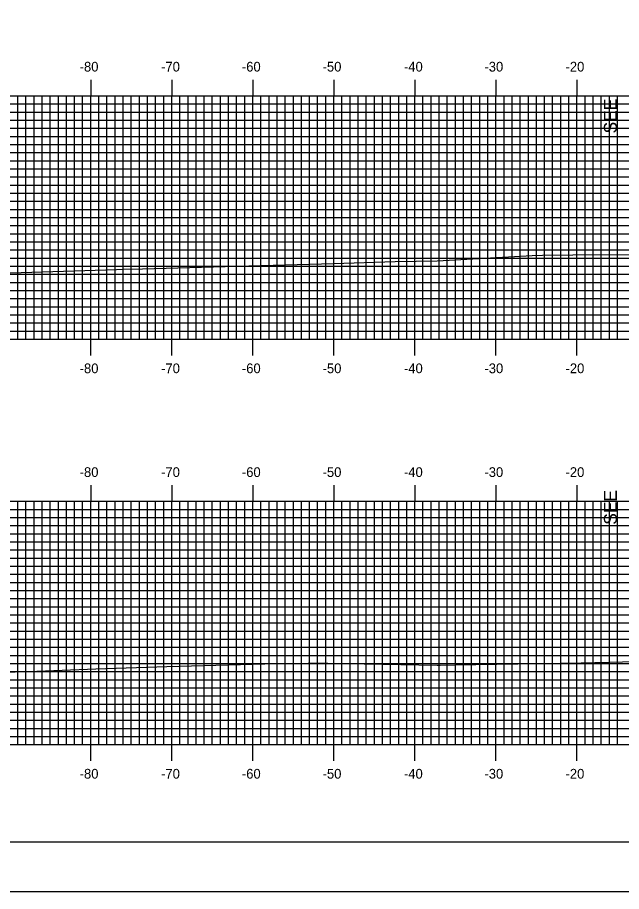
# Model space of a CAD drawing. Extents: x 1272 to 1616, y -1658 to -1438.
# Drawn here: x 1349.1 to 1423.7, y -1657.7 to -1549.9 of the extents above; entities that cross this region are included whole.
import ezdxf

# ---------------------------------------------------------------- set-up
doc = ezdxf.new("R2010")
doc.units = 0
for name, color, linetype in [('ANNOTATION', 7, 'Continuous'), ('BORDER', 7, 'Continuous'), ('H_V ANNOTATION', 7, 'Continuous'), ('MAJOR', 7, 'Continuous'), ('MINOR', 7, 'Continuous'), ('PLOT BOUNDARY', 7, 'Continuous'), ('S_Roadway_Centerline', 7, 'Continuous')]:
    doc.layers.add(name, color=color, linetype=linetype)

msp = doc.modelspace()

# ---------------------------------------------------------------- linework, layer by layer
at = {"layer": 'BORDER'}
msp.add_lwpolyline([(1288.56, -1651.6), (1608.56, -1651.6), (1608.56, -1441.6), (1288.56, -1441.6)], close=True, dxfattribs=at)
at = {"layer": 'MAJOR'}
for p, q in [((1358.16, -1557.6), (1358.16, -1559.6)), ((1368.16, -1557.6), (1368.16, -1559.6)), ((1378.16, -1557.6), (1378.16, -1559.6)), ((1388.16, -1557.6), (1388.16, -1559.6)), ((1398.16, -1557.6), (1398.16, -1559.6)), ((1408.16, -1557.6), (1408.16, -1559.6)), ((1418.16, -1557.6), (1418.16, -1559.6)), ((1298.16, -1559.6), (1578.16, -1559.6)), ((1298.16, -1559.6), (1578.16, -1559.6)), ((1358.16, -1589.6), (1358.16, -1559.6)), ((1368.16, -1589.6), (1368.16, -1559.6)), ((1378.16, -1589.6), (1378.16, -1559.6)), ((1388.16, -1589.6), (1388.16, -1559.6)), ((1398.16, -1589.6), (1398.16, -1559.6)), ((1408.16, -1589.6), (1408.16, -1559.6)), ((1418.16, -1589.6), (1418.16, -1559.6)), ((1298.16, -1564.6), (1578.16, -1564.6)), ((1298.16, -1569.6), (1578.16, -1569.6)), ((1298.16, -1574.6), (1578.16, -1574.6)), ((1298.16, -1579.6), (1578.16, -1579.6)), ((1298.16, -1584.6), (1578.16, -1584.6)), ((1298.16, -1589.6), (1578.16, -1589.6)), ((1298.16, -1589.6), (1578.16, -1589.6)), ((1358.16, -1591.61), (1358.16, -1589.6)), ((1368.16, -1591.61), (1368.16, -1589.6)), ((1378.16, -1591.61), (1378.16, -1589.6)), ((1388.16, -1591.61), (1388.16, -1589.6)), ((1398.16, -1591.61), (1398.16, -1589.6)), ((1408.16, -1591.61), (1408.16, -1589.6)), ((1418.16, -1591.61), (1418.16, -1589.6)), ((1358.16, -1607.6), (1358.16, -1609.6)), ((1368.16, -1607.6), (1368.16, -1609.6)), ((1378.16, -1607.6), (1378.16, -1609.6)), ((1388.16, -1607.6), (1388.16, -1609.6)), ((1398.16, -1607.6), (1398.16, -1609.6)), ((1408.16, -1607.6), (1408.16, -1609.6)), ((1418.16, -1607.6), (1418.16, -1609.6)), ((1298.16, -1609.6), (1578.16, -1609.6)), ((1298.16, -1609.6), (1578.16, -1609.6)), ((1358.16, -1639.6), (1358.16, -1609.6)), ((1368.16, -1639.6), (1368.16, -1609.6)), ((1378.16, -1639.6), (1378.16, -1609.6)), ((1388.16, -1639.6), (1388.16, -1609.6)), ((1398.16, -1639.6), (1398.16, -1609.6)), ((1408.16, -1639.6), (1408.16, -1609.6)), ((1418.16, -1639.6), (1418.16, -1609.6)), ((1298.16, -1614.6), (1578.16, -1614.6)), ((1298.16, -1619.6), (1578.16, -1619.6)), ((1298.16, -1624.6), (1578.16, -1624.6)), ((1298.16, -1629.6), (1578.16, -1629.6)), ((1298.16, -1634.6), (1578.16, -1634.6)), ((1298.16, -1639.6), (1578.16, -1639.6)), ((1298.16, -1639.6), (1578.16, -1639.6)), ((1358.16, -1641.61), (1358.16, -1639.6)), ((1368.16, -1641.61), (1368.16, -1639.6)), ((1378.16, -1641.61), (1378.16, -1639.6)), ((1388.16, -1641.61), (1388.16, -1639.6)), ((1398.16, -1641.61), (1398.16, -1639.6)), ((1408.16, -1641.61), (1408.16, -1639.6)), ((1418.16, -1641.61), (1418.16, -1639.6))]:
    msp.add_line(p, q, dxfattribs=at)
at = {"layer": 'MINOR'}
for p, q in [((1349.16, -1589.6), (1349.16, -1559.6)), ((1350.16, -1589.6), (1350.16, -1559.6)), ((1351.16, -1589.6), (1351.16, -1559.6)), ((1352.16, -1589.6), (1352.16, -1559.6)), ((1353.16, -1589.6), (1353.16, -1559.6)), ((1354.16, -1589.6), (1354.16, -1559.6)), ((1355.16, -1589.6), (1355.16, -1559.6)), ((1356.16, -1589.6), (1356.16, -1559.6)), ((1357.16, -1589.6), (1357.16, -1559.6)), ((1359.16, -1589.6), (1359.16, -1559.6)), ((1360.16, -1589.6), (1360.16, -1559.6)), ((1361.16, -1589.6), (1361.16, -1559.6)), ((1362.16, -1589.6), (1362.16, -1559.6)), ((1363.16, -1589.6), (1363.16, -1559.6)), ((1364.16, -1589.6), (1364.16, -1559.6)), ((1365.16, -1589.6), (1365.16, -1559.6)), ((1366.16, -1589.6), (1366.16, -1559.6)), ((1367.16, -1589.6), (1367.16, -1559.6)), ((1369.16, -1589.6), (1369.16, -1559.6)), ((1370.16, -1589.6), (1370.16, -1559.6)), ((1371.16, -1589.6), (1371.16, -1559.6)), ((1372.16, -1589.6), (1372.16, -1559.6)), ((1373.16, -1589.6), (1373.16, -1559.6)), ((1374.16, -1589.6), (1374.16, -1559.6)), ((1375.16, -1589.6), (1375.16, -1559.6)), ((1376.16, -1589.6), (1376.16, -1559.6)), ((1377.16, -1589.6), (1377.16, -1559.6)), ((1379.16, -1589.6), (1379.16, -1559.6)), ((1380.16, -1589.6), (1380.16, -1559.6)), ((1381.16, -1589.6), (1381.16, -1559.6)), ((1382.16, -1589.6), (1382.16, -1559.6)), ((1383.16, -1589.6), (1383.16, -1559.6)), ((1384.16, -1589.6), (1384.16, -1559.6)), ((1385.16, -1589.6), (1385.16, -1559.6)), ((1386.16, -1589.6), (1386.16, -1559.6)), ((1387.16, -1589.6), (1387.16, -1559.6)), ((1389.16, -1589.6), (1389.16, -1559.6)), ((1390.16, -1589.6), (1390.16, -1559.6)), ((1391.16, -1589.6), (1391.16, -1559.6)), ((1392.16, -1589.6), (1392.16, -1559.6)), ((1393.16, -1589.6), (1393.16, -1559.6)), ((1394.16, -1589.6), (1394.16, -1559.6)), ((1395.16, -1589.6), (1395.16, -1559.6)), ((1396.16, -1589.6), (1396.16, -1559.6)), ((1397.16, -1589.6), (1397.16, -1559.6)), ((1399.16, -1589.6), (1399.16, -1559.6)), ((1400.16, -1589.6), (1400.16, -1559.6)), ((1401.16, -1589.6), (1401.16, -1559.6)), ((1402.16, -1589.6), (1402.16, -1559.6)), ((1403.16, -1589.6), (1403.16, -1559.6)), ((1404.16, -1589.6), (1404.16, -1559.6)), ((1405.16, -1589.6), (1405.16, -1559.6)), ((1406.16, -1589.6), (1406.16, -1559.6)), ((1407.16, -1589.6), (1407.16, -1559.6)), ((1409.16, -1589.6), (1409.16, -1559.6)), ((1410.16, -1589.6), (1410.16, -1559.6)), ((1411.16, -1589.6), (1411.16, -1559.6)), ((1412.16, -1589.6), (1412.16, -1559.6)), ((1413.16, -1589.6), (1413.16, -1559.6)), ((1414.16, -1589.6), (1414.16, -1559.6)), ((1415.16, -1589.6), (1415.16, -1559.6)), ((1416.16, -1589.6), (1416.16, -1559.6)), ((1417.16, -1589.6), (1417.16, -1559.6)), ((1419.16, -1589.6), (1419.16, -1559.6)), ((1420.16, -1589.6), (1420.16, -1559.6)), ((1421.16, -1589.6), (1421.16, -1559.6)), ((1422.16, -1589.6), (1422.16, -1559.6)), ((1423.16, -1589.6), (1423.16, -1559.6)), ((1298.16, -1560.6), (1578.16, -1560.6)), ((1298.16, -1561.6), (1578.16, -1561.6)), ((1298.16, -1562.6), (1578.16, -1562.6)), ((1298.16, -1563.6), (1578.16, -1563.6)), ((1298.16, -1565.6), (1578.16, -1565.6)), ((1298.16, -1566.6), (1578.16, -1566.6)), ((1298.16, -1567.6), (1578.16, -1567.6)), ((1298.16, -1568.6), (1578.16, -1568.6)), ((1298.16, -1570.6), (1578.16, -1570.6)), ((1298.16, -1571.6), (1578.16, -1571.6)), ((1298.16, -1572.6), (1578.16, -1572.6)), ((1298.16, -1573.6), (1578.16, -1573.6)), ((1298.16, -1575.6), (1578.16, -1575.6)), ((1298.16, -1576.6), (1578.16, -1576.6)), ((1298.16, -1577.6), (1578.16, -1577.6)), ((1298.16, -1578.6), (1578.16, -1578.6)), ((1298.16, -1580.6), (1578.16, -1580.6)), ((1298.16, -1581.6), (1578.16, -1581.6)), ((1298.16, -1582.6), (1578.16, -1582.6)), ((1298.16, -1583.6), (1578.16, -1583.6)), ((1298.16, -1585.6), (1578.16, -1585.6)), ((1298.16, -1586.6), (1578.16, -1586.6)), ((1298.16, -1587.6), (1578.16, -1587.6)), ((1298.16, -1588.6), (1578.16, -1588.6)), ((1349.16, -1639.6), (1349.16, -1609.6)), ((1350.16, -1639.6), (1350.16, -1609.6)), ((1351.16, -1639.6), (1351.16, -1609.6)), ((1352.16, -1639.6), (1352.16, -1609.6)), ((1353.16, -1639.6), (1353.16, -1609.6)), ((1354.16, -1639.6), (1354.16, -1609.6)), ((1355.16, -1639.6), (1355.16, -1609.6)), ((1356.16, -1639.6), (1356.16, -1609.6)), ((1357.16, -1639.6), (1357.16, -1609.6)), ((1359.16, -1639.6), (1359.16, -1609.6)), ((1360.16, -1639.6), (1360.16, -1609.6)), ((1361.16, -1639.6), (1361.16, -1609.6)), ((1362.16, -1639.6), (1362.16, -1609.6)), ((1363.16, -1639.6), (1363.16, -1609.6)), ((1364.16, -1639.6), (1364.16, -1609.6)), ((1365.16, -1639.6), (1365.16, -1609.6)), ((1366.16, -1639.6), (1366.16, -1609.6)), ((1367.16, -1639.6), (1367.16, -1609.6)), ((1369.16, -1639.6), (1369.16, -1609.6)), ((1370.16, -1639.6), (1370.16, -1609.6)), ((1371.16, -1639.6), (1371.16, -1609.6)), ((1372.16, -1639.6), (1372.16, -1609.6)), ((1373.16, -1639.6), (1373.16, -1609.6)), ((1374.16, -1639.6), (1374.16, -1609.6)), ((1375.16, -1639.6), (1375.16, -1609.6)), ((1376.16, -1639.6), (1376.16, -1609.6)), ((1377.16, -1639.6), (1377.16, -1609.6)), ((1379.16, -1639.6), (1379.16, -1609.6)), ((1380.16, -1639.6), (1380.16, -1609.6)), ((1381.16, -1639.6), (1381.16, -1609.6)), ((1382.16, -1639.6), (1382.16, -1609.6)), ((1383.16, -1639.6), (1383.16, -1609.6)), ((1384.16, -1639.6), (1384.16, -1609.6)), ((1385.16, -1639.6), (1385.16, -1609.6)), ((1386.16, -1639.6), (1386.16, -1609.6)), ((1387.16, -1639.6), (1387.16, -1609.6)), ((1389.16, -1639.6), (1389.16, -1609.6)), ((1390.16, -1639.6), (1390.16, -1609.6)), ((1391.16, -1639.6), (1391.16, -1609.6)), ((1392.16, -1639.6), (1392.16, -1609.6)), ((1393.16, -1639.6), (1393.16, -1609.6)), ((1394.16, -1639.6), (1394.16, -1609.6)), ((1395.16, -1639.6), (1395.16, -1609.6)), ((1396.16, -1639.6), (1396.16, -1609.6)), ((1397.16, -1639.6), (1397.16, -1609.6)), ((1399.16, -1639.6), (1399.16, -1609.6)), ((1400.16, -1639.6), (1400.16, -1609.6)), ((1401.16, -1639.6), (1401.16, -1609.6)), ((1402.16, -1639.6), (1402.16, -1609.6)), ((1403.16, -1639.6), (1403.16, -1609.6)), ((1404.16, -1639.6), (1404.16, -1609.6)), ((1405.16, -1639.6), (1405.16, -1609.6)), ((1406.16, -1639.6), (1406.16, -1609.6)), ((1407.16, -1639.6), (1407.16, -1609.6)), ((1409.16, -1639.6), (1409.16, -1609.6)), ((1410.16, -1639.6), (1410.16, -1609.6)), ((1411.16, -1639.6), (1411.16, -1609.6)), ((1412.16, -1639.6), (1412.16, -1609.6)), ((1413.16, -1639.6), (1413.16, -1609.6)), ((1414.16, -1639.6), (1414.16, -1609.6)), ((1415.16, -1639.6), (1415.16, -1609.6)), ((1416.16, -1639.6), (1416.16, -1609.6)), ((1417.16, -1639.6), (1417.16, -1609.6)), ((1419.16, -1639.6), (1419.16, -1609.6)), ((1420.16, -1639.6), (1420.16, -1609.6)), ((1421.16, -1639.6), (1421.16, -1609.6)), ((1422.16, -1639.6), (1422.16, -1609.6)), ((1423.16, -1639.6), (1423.16, -1609.6)), ((1298.16, -1610.6), (1578.16, -1610.6)), ((1298.16, -1611.6), (1578.16, -1611.6)), ((1298.16, -1612.6), (1578.16, -1612.6)), ((1298.16, -1613.6), (1578.16, -1613.6)), ((1298.16, -1615.6), (1578.16, -1615.6)), ((1298.16, -1616.6), (1578.16, -1616.6)), ((1298.16, -1617.6), (1578.16, -1617.6)), ((1298.16, -1618.6), (1578.16, -1618.6)), ((1298.16, -1620.6), (1578.16, -1620.6)), ((1298.16, -1621.6), (1578.16, -1621.6)), ((1298.16, -1622.6), (1578.16, -1622.6)), ((1298.16, -1623.6), (1578.16, -1623.6)), ((1298.16, -1625.6), (1578.16, -1625.6)), ((1298.16, -1626.6), (1578.16, -1626.6)), ((1298.16, -1627.6), (1578.16, -1627.6)), ((1298.16, -1628.6), (1578.16, -1628.6)), ((1298.16, -1630.6), (1578.16, -1630.6)), ((1298.16, -1631.6), (1578.16, -1631.6)), ((1298.16, -1632.6), (1578.16, -1632.6)), ((1298.16, -1633.6), (1578.16, -1633.6)), ((1298.16, -1635.6), (1578.16, -1635.6)), ((1298.16, -1636.6), (1578.16, -1636.6)), ((1298.16, -1637.6), (1578.16, -1637.6)), ((1298.16, -1638.6), (1578.16, -1638.6))]:
    msp.add_line(p, q, dxfattribs=at)
at = {"layer": 'PLOT BOUNDARY'}
msp.add_lwpolyline([(1272.37, -1657.72), (1612.37, -1657.72), (1612.37, -1437.72), (1272.37, -1437.72)], close=True, dxfattribs=at)
at = {"layer": 'S_Roadway_Centerline'}
for points in [[(1298.16, -1583.56), (1307.94, -1583.03), (1309.29, -1582.94), (1312.15, -1582.8), (1322.73, -1582.22), (1325.46, -1582.08), (1331.67, -1581.99), (1343.52, -1581.4), (1348.24, -1581.42), (1361.34, -1581), (1362.22, -1580.99), (1364.56, -1580.94), (1377.65, -1580.55), (1388.11, -1580.26), (1395.72, -1580.04), (1400.92, -1579.96), (1412.64, -1579.29), (1413.89, -1579.26), (1417.66, -1579.21), (1430.51, -1579.17)], [(1298.16, -1633.74), (1300.46, -1633.57), (1301.96, -1633.44), (1306.95, -1633.01), (1317.46, -1632.09), (1329.31, -1631.5), (1333.41, -1631.31), (1343.82, -1630.75), (1350.46, -1630.57), (1358.78, -1630.24), (1367.55, -1629.97), (1381.18, -1629.6), (1384.99, -1629.58), (1387.41, -1629.56), (1400.91, -1629.81), (1401.27, -1629.81), (1403.07, -1629.78), (1418.67, -1629.53), (1427.2, -1629.3)]]:
    msp.add_lwpolyline(points, dxfattribs=at)

# ---------------------------------------------------------------- texts
at = {"layer": 'ANNOTATION'}
for p in [(1423.09, -1564.23), (1423.09, -1612.49)]:
    msp.add_text('SEE', height=1.6, rotation=90, dxfattribs=at).set_placement(p)
at = {"layer": 'H_V ANNOTATION'}
for s, p in [('-80', (1356.79, -1556.6)), ('-70', (1366.84, -1556.6)), ('-60', (1376.81, -1556.6)), ('-50', (1386.77, -1556.6)), ('-40', (1396.81, -1556.6)), ('-30', (1406.74, -1556.6)), ('-20', (1416.75, -1556.6)), ('-80', (1356.79, -1593.8)), ('-70', (1366.84, -1593.8)), ('-60', (1376.81, -1593.8)), ('-50', (1386.77, -1593.8)), ('-40', (1396.81, -1593.8)), ('-30', (1406.74, -1593.8)), ('-20', (1416.75, -1593.8)), ('-80', (1356.79, -1606.6)), ('-70', (1366.84, -1606.6)), ('-60', (1376.81, -1606.6)), ('-50', (1386.77, -1606.6)), ('-40', (1396.81, -1606.6)), ('-30', (1406.74, -1606.6)), ('-20', (1416.75, -1606.6)), ('-80', (1356.79, -1643.8)), ('-70', (1366.84, -1643.8)), ('-60', (1376.81, -1643.8)), ('-50', (1386.77, -1643.8)), ('-40', (1396.81, -1643.8)), ('-30', (1406.74, -1643.8)), ('-20', (1416.75, -1643.8))]:
    msp.add_text(s, height=1.2, dxfattribs=at).set_placement(p)

doc.saveas('drawing.dxf')
